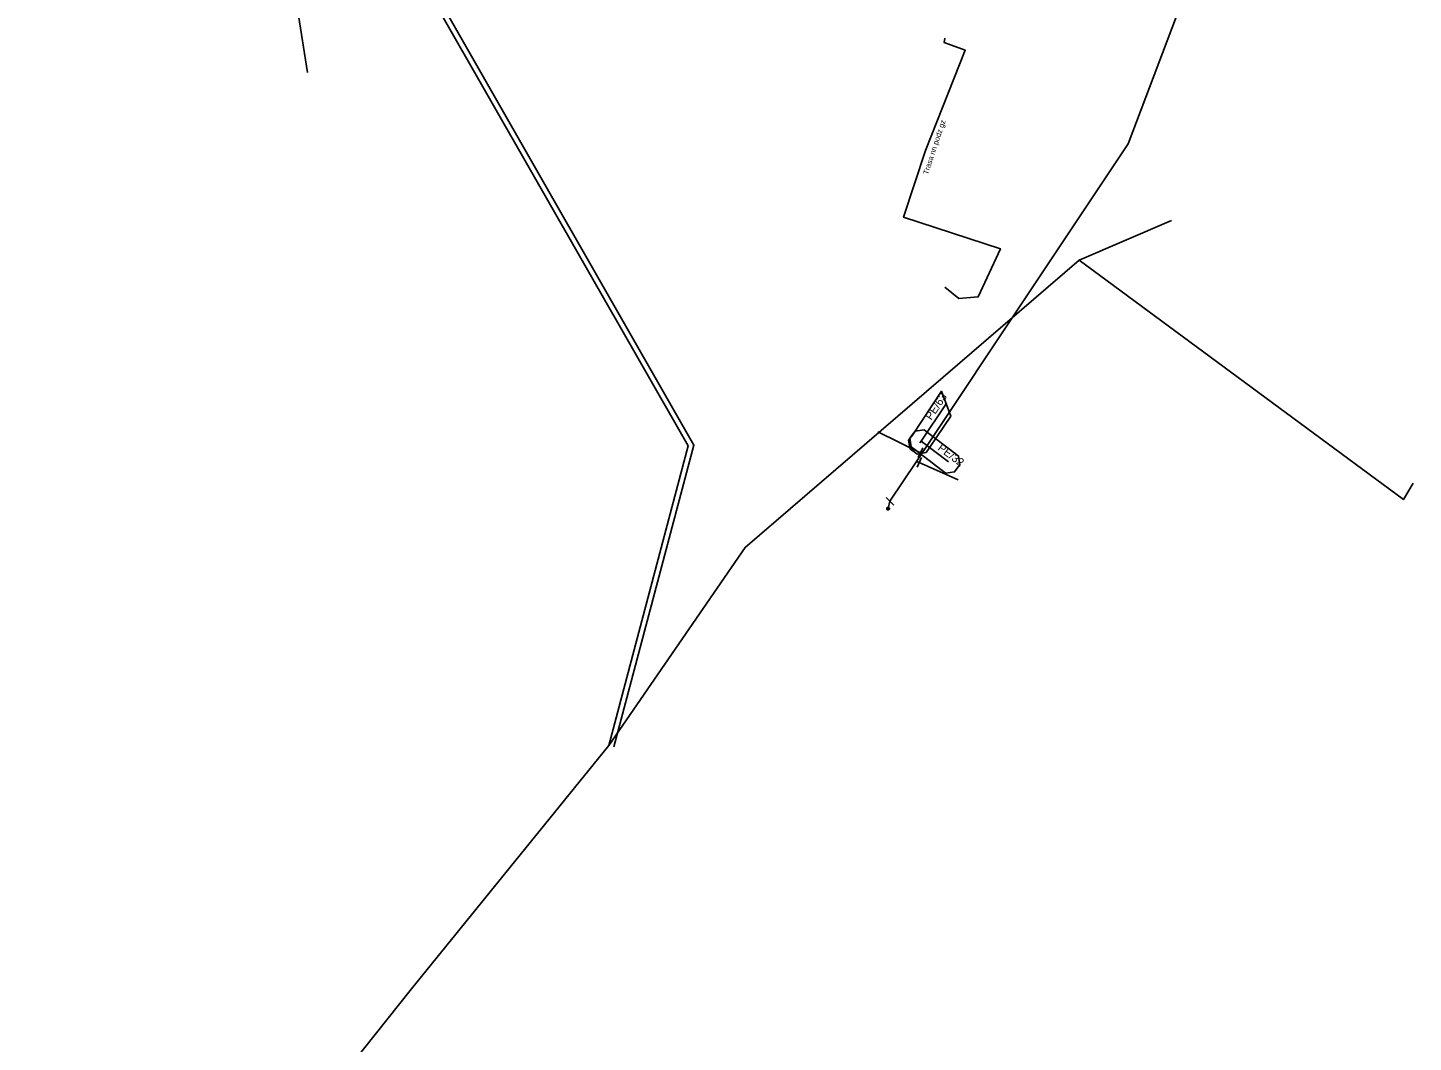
# Model space of a CAD drawing. Extents: x -743072 to -742584, y -978827 to -978325.
# Drawn here: x -742818.7 to -742688.8, y -978731.6 to -978636.5 of the extents above; entities that cross this region are included whole.
import ezdxf

# ---------------------------------------------------------------- set-up
doc = ezdxf.new("R2010")
doc.units = 0
for name, color, linetype in [('IS_CETIN_sdělovací kabel_nadz', 7, 'Continuous'), ('IS_CEZ_NN_podz', 7, 'Continuous'), ('IS_GasNet_ochr pasmo', 7, 'Continuous'), ('IS_GasNet_plyn STL', 7, 'Continuous'), ('IS_Obec_kabel VO_nadz', 7, 'Continuous'), ('IS_popis_CEZ', 7, 'Continuous'), ('IS_popis_GasNet', 7, 'Continuous'), ('IS_ScVK_Kanal_dest', 7, 'Continuous'), ('IS_ScVK_Vodovod', 7, 'Continuous')]:
    doc.layers.add(name, color=color, linetype=linetype)

msp = doc.modelspace()

# ---------------------------------------------------------------- linework, layer by layer
at = {"layer": 'IS_CETIN_sdělovací kabel_nadz'}
for points in [[(-742764.24, -978703.78), (-742756.8, -978675.7), (-742780.28, -978634.66), (-742755.96, -978617.33)], [(-742720.15, -978658.28), (-742711.48, -978654.57)], [(-742764.24, -978703.78), (-742751.467, -978685.2), (-742720.15, -978658.28)], [(-742720.15, -978658.28), (-742689.748, -978680.72), (-742688.825, -978679.175)], [(-742948.6, -978798.15), (-742924.18, -978801.88), (-742894.32, -978819.74), (-742863.53, -978826.65), (-742839.69, -978796.96), (-742810.33, -978761.23), (-742782.75, -978726.57), (-742764.24, -978703.78)]]:
    msp.add_lwpolyline(points, dxfattribs=at)
at = {"layer": 'IS_CEZ_NN_podz'}
msp.add_lwpolyline([(-742732.729, -978637.471), (-742732.797, -978637.896), (-742730.827, -978638.612), (-742734.55, -978648), (-742736.602, -978654.26), (-742727.525, -978657.225), (-742729.601, -978661.74), (-742731.42, -978661.87), (-742732.74, -978660.821)], dxfattribs=at)
at = {"layer": 'IS_GasNet_ochr pasmo'}
for points in [[(-742735.784, -978674.673), (-742733.041, -978670.576), (-742732.189, -978672.899), (-742734.136, -978675.807), (-742734.263, -978675.987), (-742734.502, -978676.325), (-742735.319, -978676.466), (-742735.657, -978676.227), (-742735.995, -978675.988), (-742736.136, -978675.171), (-742735.897, -978674.833)], [(-742734.688, -978674.192), (-742734.357, -978674.442), (-742731.777, -978676.392), (-742731.446, -978676.642), (-742731.332, -978677.462), (-742731.582, -978677.793), (-742731.832, -978678.124), (-742732.652, -978678.238), (-742732.983, -978677.988), (-742735.563, -978676.038), (-742735.894, -978675.788), (-742736.008, -978674.968), (-742735.758, -978674.637), (-742735.508, -978674.306)]]:
    msp.add_lwpolyline(points, close=True, dxfattribs=at)
at = {"layer": 'IS_GasNet_plyn STL'}
for points in [[(-742735.08, -978675.41), (-742734.96, -978675.24), (-742732.615, -978671.738)], [(-742734.96, -978675.24), (-742732.38, -978677.19)]]:
    msp.add_lwpolyline(points, dxfattribs=at)
at = {"layer": 'IS_Obec_kabel VO_nadz'}
msp.add_lwpolyline([(-742763.757, -978703.908), (-742756.264, -978675.63), (-742779.621, -978634.805), (-742755.67, -978617.737)], dxfattribs=at)
at = {"layer": 'IS_ScVK_Kanal_dest'}
for points in [[(-742735.02, -978676.329), (-742734.894, -978676.393)], [(-742735.14, -978677.239), (-742735.409, -978677.167)]]:
    msp.add_lwpolyline(points, dxfattribs=at)
at = {"layer": 'IS_ScVK_Vodovod'}
for points in [[(-742798.469, -978602.67), (-742792.475, -978640.717)], [(-742706.569, -978620.537), (-742706.695, -978621.62), (-742710.69, -978634.52), (-742715.539, -978647.389), (-742724.81, -978661.243), (-742734.894, -978676.393), (-742735.409, -978677.167), (-742737.884, -978680.886)], [(-742735.02, -978676.329), (-742739.028, -978674.364)], [(-742735.239, -978676.778), (-742734.799, -978675.88)], [(-742734.937, -978676.782), (-742735.343, -978677.695)], [(-742735.14, -978677.239), (-742731.495, -978678.863)], [(-742738.243, -978680.538), (-742737.525, -978681.234)], [(-742738.185, -978681.57), (-742738.185, -978681.583), (-742738.183, -978681.596), (-742738.18, -978681.609), (-742738.175, -978681.621), (-742738.169, -978681.633), (-742738.162, -978681.644), (-742738.154, -978681.654), (-742738.144, -978681.664), (-742738.134, -978681.672), (-742738.123, -978681.679), (-742738.111, -978681.685), (-742738.099, -978681.69), (-742738.086, -978681.693), (-742738.073, -978681.695), (-742738.06, -978681.697), (-742738.047, -978681.696), (-742738.034, -978681.694), (-742738.021, -978681.691), (-742738.009, -978681.686), (-742737.997, -978681.68), (-742737.986, -978681.673), (-742737.976, -978681.665), (-742737.966, -978681.655), (-742737.958, -978681.645), (-742737.951, -978681.634), (-742737.945, -978681.622), (-742737.94, -978681.61), (-742737.937, -978681.597), (-742737.935, -978681.584), (-742737.933, -978681.571), (-742737.934, -978681.558), (-742737.936, -978681.545), (-742737.939, -978681.532), (-742737.944, -978681.52), (-742737.95, -978681.508), (-742737.957, -978681.497), (-742737.965, -978681.487), (-742737.975, -978681.477), (-742737.985, -978681.469), (-742737.996, -978681.462), (-742738.008, -978681.456), (-742738.02, -978681.451), (-742738.033, -978681.448), (-742738.046, -978681.446), (-742738.059, -978681.445), (-742738.072, -978681.445), (-742738.085, -978681.447), (-742738.098, -978681.45), (-742738.11, -978681.455), (-742738.122, -978681.461), (-742738.133, -978681.468), (-742738.143, -978681.476), (-742738.153, -978681.486), (-742738.161, -978681.496), (-742738.168, -978681.507), (-742738.174, -978681.519), (-742738.179, -978681.531), (-742738.182, -978681.544), (-742738.184, -978681.557), (-742738.185, -978681.57)], [(-742738.165, -978681.57), (-742738.166, -978681.581), (-742738.164, -978681.592), (-742738.161, -978681.603), (-742738.157, -978681.613), (-742738.152, -978681.623), (-742738.146, -978681.632), (-742738.139, -978681.641), (-742738.131, -978681.649), (-742738.122, -978681.656), (-742738.113, -978681.662), (-742738.103, -978681.667), (-742738.093, -978681.671), (-742738.082, -978681.674), (-742738.071, -978681.677), (-742738.06, -978681.677), (-742738.049, -978681.677), (-742738.038, -978681.675), (-742738.027, -978681.672), (-742738.017, -978681.668), (-742738.007, -978681.663), (-742737.998, -978681.657), (-742737.989, -978681.65), (-742737.981, -978681.642), (-742737.974, -978681.633), (-742737.968, -978681.624), (-742737.963, -978681.614), (-742737.959, -978681.604), (-742737.956, -978681.593), (-742737.954, -978681.582), (-742737.953, -978681.571), (-742737.953, -978681.56), (-742737.955, -978681.549), (-742737.958, -978681.538), (-742737.962, -978681.528), (-742737.967, -978681.518), (-742737.973, -978681.509), (-742737.98, -978681.5), (-742737.988, -978681.492), (-742737.997, -978681.485), (-742738.006, -978681.479), (-742738.016, -978681.474), (-742738.026, -978681.47), (-742738.037, -978681.467), (-742738.048, -978681.465), (-742738.059, -978681.465), (-742738.07, -978681.464), (-742738.081, -978681.466), (-742738.092, -978681.469), (-742738.102, -978681.473), (-742738.112, -978681.478), (-742738.121, -978681.484), (-742738.13, -978681.491), (-742738.138, -978681.499), (-742738.145, -978681.508), (-742738.151, -978681.517), (-742738.156, -978681.527), (-742738.16, -978681.537), (-742738.163, -978681.548), (-742738.165, -978681.559), (-742738.165, -978681.57)], [(-742738.146, -978681.57), (-742738.146, -978681.579), (-742738.145, -978681.588), (-742738.142, -978681.597), (-742738.139, -978681.605), (-742738.135, -978681.613), (-742738.13, -978681.621), (-742738.124, -978681.628), (-742738.118, -978681.634), (-742738.111, -978681.64), (-742738.103, -978681.645), (-742738.095, -978681.649), (-742738.087, -978681.652), (-742738.078, -978681.655), (-742738.069, -978681.656), (-742738.06, -978681.658), (-742738.051, -978681.657), (-742738.042, -978681.656), (-742738.033, -978681.653), (-742738.025, -978681.65), (-742738.017, -978681.646), (-742738.009, -978681.641), (-742738.002, -978681.635), (-742737.996, -978681.629), (-742737.99, -978681.622), (-742737.985, -978681.614), (-742737.981, -978681.606), (-742737.978, -978681.598), (-742737.975, -978681.589), (-742737.974, -978681.58), (-742737.972, -978681.571), (-742737.973, -978681.562), (-742737.974, -978681.553), (-742737.977, -978681.544), (-742737.98, -978681.536), (-742737.984, -978681.528), (-742737.989, -978681.52), (-742737.995, -978681.513), (-742738.001, -978681.507), (-742738.008, -978681.501), (-742738.016, -978681.496), (-742738.024, -978681.492), (-742738.032, -978681.489), (-742738.041, -978681.486), (-742738.05, -978681.485), (-742738.059, -978681.484), (-742738.068, -978681.484), (-742738.077, -978681.485), (-742738.086, -978681.488), (-742738.094, -978681.491), (-742738.102, -978681.495), (-742738.11, -978681.5), (-742738.117, -978681.506), (-742738.123, -978681.512), (-742738.129, -978681.519), (-742738.134, -978681.527), (-742738.138, -978681.535), (-742738.141, -978681.543), (-742738.144, -978681.552), (-742738.145, -978681.561), (-742738.146, -978681.57)], [(-742738.126, -978681.57), (-742738.126, -978681.577), (-742738.125, -978681.584), (-742738.124, -978681.591), (-742738.121, -978681.597), (-742738.118, -978681.603), (-742738.114, -978681.609), (-742738.11, -978681.615), (-742738.105, -978681.62), (-742738.099, -978681.624), (-742738.093, -978681.628), (-742738.087, -978681.631), (-742738.081, -978681.634), (-742738.074, -978681.635), (-742738.067, -978681.638), (-742738.06, -978681.638), (-742738.053, -978681.638), (-742738.046, -978681.636), (-742738.039, -978681.635), (-742738.033, -978681.632), (-742738.026, -978681.629), (-742738.021, -978681.625), (-742738.015, -978681.621), (-742738.01, -978681.616), (-742738.006, -978681.61), (-742738.002, -978681.604), (-742737.999, -978681.598), (-742737.996, -978681.592), (-742737.994, -978681.585), (-742737.993, -978681.578), (-742737.992, -978681.571), (-742737.992, -978681.564), (-742737.993, -978681.557), (-742737.995, -978681.55), (-742737.998, -978681.544), (-742738.001, -978681.537), (-742738.005, -978681.532), (-742738.009, -978681.526), (-742738.014, -978681.521), (-742738.02, -978681.517), (-742738.025, -978681.513), (-742738.032, -978681.51), (-742738.038, -978681.507), (-742738.045, -978681.505), (-742738.052, -978681.504), (-742738.059, -978681.504), (-742738.066, -978681.504), (-742738.073, -978681.504), (-742738.08, -978681.506), (-742738.086, -978681.509), (-742738.092, -978681.512), (-742738.098, -978681.516), (-742738.104, -978681.52), (-742738.109, -978681.525), (-742738.113, -978681.531), (-742738.117, -978681.536), (-742738.12, -978681.543), (-742738.123, -978681.549), (-742738.124, -978681.556), (-742738.126, -978681.563), (-742738.126, -978681.57)], [(-742738.106, -978681.57), (-742738.106, -978681.575), (-742738.106, -978681.58), (-742738.105, -978681.585), (-742738.103, -978681.589), (-742738.101, -978681.594), (-742738.098, -978681.598), (-742738.095, -978681.601), (-742738.091, -978681.605), (-742738.088, -978681.608), (-742738.084, -978681.611), (-742738.079, -978681.613), (-742738.075, -978681.615), (-742738.07, -978681.616), (-742738.065, -978681.618), (-742738.06, -978681.618), (-742738.055, -978681.618), (-742738.05, -978681.617), (-742738.045, -978681.616), (-742738.041, -978681.614), (-742738.036, -978681.612), (-742738.032, -978681.609), (-742738.028, -978681.606), (-742738.025, -978681.602), (-742738.022, -978681.599), (-742738.019, -978681.595), (-742738.017, -978681.59), (-742738.015, -978681.586), (-742738.014, -978681.581), (-742738.013, -978681.576), (-742738.012, -978681.571), (-742738.012, -978681.566), (-742738.013, -978681.561), (-742738.014, -978681.556), (-742738.016, -978681.552), (-742738.018, -978681.547), (-742738.021, -978681.543), (-742738.024, -978681.539), (-742738.027, -978681.536), (-742738.031, -978681.533), (-742738.035, -978681.53), (-742738.04, -978681.528), (-742738.044, -978681.526), (-742738.049, -978681.525), (-742738.054, -978681.524), (-742738.059, -978681.524), (-742738.064, -978681.524), (-742738.069, -978681.525), (-742738.074, -978681.525), (-742738.078, -978681.527), (-742738.083, -978681.529), (-742738.087, -978681.532), (-742738.09, -978681.535), (-742738.094, -978681.538), (-742738.097, -978681.542), (-742738.1, -978681.546), (-742738.102, -978681.551), (-742738.104, -978681.555), (-742738.105, -978681.56), (-742738.106, -978681.565), (-742738.106, -978681.57)], [(-742737.884, -978680.886), (-742738.059, -978681.57)], [(-742738.086, -978681.57), (-742738.086, -978681.573), (-742738.087, -978681.576), (-742738.086, -978681.578), (-742738.085, -978681.581), (-742738.084, -978681.584), (-742738.082, -978681.586), (-742738.08, -978681.588), (-742738.078, -978681.59), (-742738.076, -978681.592), (-742738.074, -978681.594), (-742738.071, -978681.596), (-742738.068, -978681.597), (-742738.066, -978681.597), (-742738.063, -978681.598), (-742738.06, -978681.598), (-742738.057, -978681.598), (-742738.054, -978681.598), (-742738.051, -978681.597), (-742738.049, -978681.596), (-742738.046, -978681.595), (-742738.044, -978681.593), (-742738.041, -978681.591), (-742738.039, -978681.589), (-742738.038, -978681.587), (-742738.036, -978681.585), (-742738.035, -978681.582), (-742738.033, -978681.579), (-742738.033, -978681.577), (-742738.032, -978681.574), (-742738.031, -978681.571), (-742738.032, -978681.568), (-742738.032, -978681.565), (-742738.033, -978681.562), (-742738.034, -978681.56), (-742738.035, -978681.557), (-742738.037, -978681.555), (-742738.038, -978681.552), (-742738.04, -978681.55), (-742738.043, -978681.549), (-742738.045, -978681.547), (-742738.048, -978681.546), (-742738.05, -978681.545), (-742738.053, -978681.544), (-742738.056, -978681.544), (-742738.059, -978681.543), (-742738.062, -978681.544), (-742738.065, -978681.543), (-742738.067, -978681.545), (-742738.07, -978681.545), (-742738.073, -978681.546), (-742738.075, -978681.548), (-742738.077, -978681.549), (-742738.079, -978681.551), (-742738.081, -978681.554), (-742738.083, -978681.556), (-742738.084, -978681.559), (-742738.085, -978681.561), (-742738.086, -978681.564), (-742738.086, -978681.567), (-742738.086, -978681.57)], [(-742738.067, -978681.57), (-742738.067, -978681.572), (-742738.067, -978681.572), (-742738.066, -978681.572), (-742738.066, -978681.574), (-742738.067, -978681.575), (-742738.065, -978681.575), (-742738.065, -978681.575), (-742738.065, -978681.577), (-742738.065, -978681.577), (-742738.064, -978681.578), (-742738.062, -978681.578), (-742738.062, -978681.578), (-742738.062, -978681.579), (-742738.06, -978681.579), (-742738.06, -978681.579), (-742738.059, -978681.579), (-742738.058, -978681.579), (-742738.058, -978681.578), (-742738.057, -978681.578), (-742738.055, -978681.578), (-742738.055, -978681.577), (-742738.055, -978681.577), (-742738.054, -978681.576), (-742738.054, -978681.576), (-742738.052, -978681.575), (-742738.052, -978681.574), (-742738.051, -978681.573), (-742738.051, -978681.573), (-742738.051, -978681.572), (-742738.051, -978681.571), (-742738.051, -978681.57), (-742738.051, -978681.569), (-742738.051, -978681.569), (-742738.052, -978681.568), (-742738.052, -978681.567), (-742738.053, -978681.566), (-742738.053, -978681.566), (-742738.054, -978681.565), (-742738.054, -978681.565), (-742738.055, -978681.564), (-742738.056, -978681.564), (-742738.057, -978681.563), (-742738.057, -978681.563), (-742738.058, -978681.563), (-742738.059, -978681.563), (-742738.06, -978681.563), (-742738.061, -978681.563), (-742738.061, -978681.563), (-742738.062, -978681.564), (-742738.063, -978681.563), (-742738.064, -978681.565), (-742738.064, -978681.565), (-742738.065, -978681.565), (-742738.065, -978681.565), (-742738.066, -978681.567), (-742738.066, -978681.568), (-742738.066, -978681.569), (-742738.067, -978681.569), (-742738.067, -978681.57), (-742738.067, -978681.57)]]:
    msp.add_lwpolyline(points, dxfattribs=at)

# ---------------------------------------------------------------- texts
at = {"layer": 'IS_popis_CEZ'}
msp.add_text('Trasa nn podz gz', height=0.5, rotation=71.85109, dxfattribs=at).set_placement((-742734.319, -978650.31))
at = {"layer": 'IS_popis_GasNet'}
for s, rotation, p in [('PE/63', 56.19688, (-742734.018, -978673.334)), ('PE/32', 322.9175, (-742733.47, -978676.015))]:
    msp.add_text(s, height=0.75, rotation=rotation, dxfattribs=at).set_placement(p)

doc.saveas('drawing.dxf')
